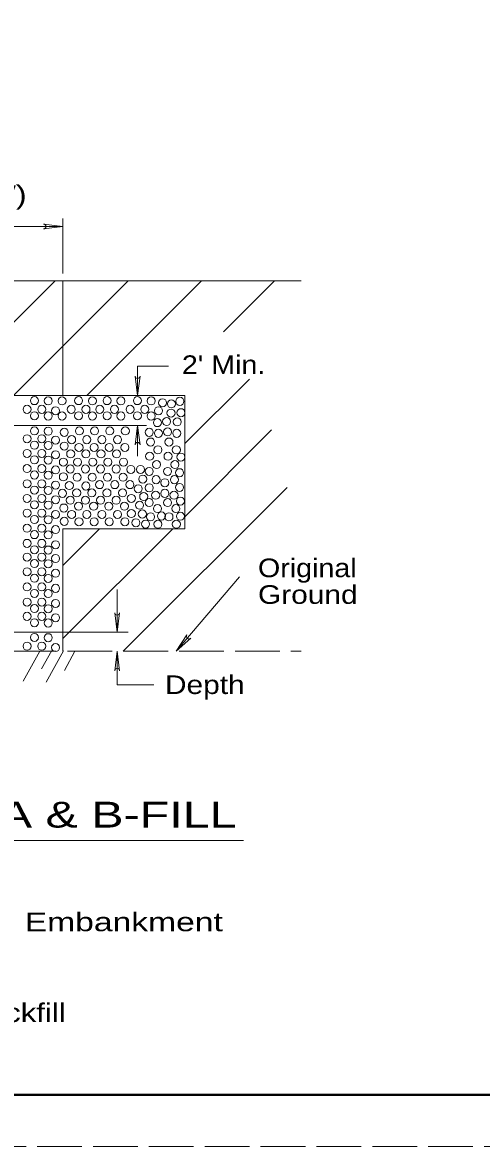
# Model space of a CAD drawing. Extents: x 750.7 to 784.7, y 834.8 to 878.8.
# Drawn here: x 758.61 to 763.05, y 834.78 to 845.66 of the extents above; entities that cross this region are included whole.
import ezdxf

# ---------------------------------------------------------------- set-up
doc = ezdxf.new("R2010")
doc.units = 0
doc.header["$LTSCALE"] = 0.072
doc.linetypes.add('LONG_DASHED', pattern=[7.5, 6, -1.5])
doc.layers.add('1', color=7, linetype='Continuous', lineweight=13)
doc.layers.add('47', color=7, linetype='Continuous', lineweight=13)

msp = doc.modelspace()

# ---------------------------------------------------------------- linework, layer by layer
at = {"layer": '1'}
for p, q in [((755.99883, 843.68525), (758.99883, 843.68525)), ((758.99883, 843.2315), (758.99883, 843.76325)), ((754.18342, 843.15875), (761.30275, 843.15875)), ((757.81558, 842.05058), (758.92367, 843.15875)), ((758.52258, 842.05058), (759.63067, 843.15875)), ((758.99883, 843.15875), (758.99883, 842.05058)), ((759.22958, 842.05058), (760.33775, 843.15875)), ((760.55258, 842.6665), (761.04483, 843.15875)), ((759.72125, 842.05058), (759.72125, 842.33475)), ((759.72125, 842.33475), (760.02133, 842.33475)), ((760.17767, 841.58442), (760.803, 842.20975)), ((754.82, 842.05058), (760.17767, 842.05058)), ((759.09983, 842.05058), (759.80117, 842.05058)), ((757.86583, 841.76058), (759.80658, 841.76058)), ((759.72125, 841.46442), (759.72125, 841.76058)), ((760.17767, 840.87725), (761.01733, 841.717)), ((759.58325, 839.5755), (761.16675, 841.15917)), ((758.99883, 840.76083), (758.99883, 839.5755)), ((758.99883, 840.40542), (759.35417, 840.76083)), ((758.99883, 839.69825), (760.06125, 840.76083)), ((760.0955, 839.5755), (760.70658, 840.29742)), ((759.52417, 839.76083), (759.52417, 840.17458)), ((757.72442, 839.76083), (759.63075, 839.76083)), ((758.77467, 839.57825), (758.61408, 839.28725)), ((758.89183, 839.58358), (758.79342, 839.40517)), ((759.00383, 839.57967), (758.83767, 839.2785)), ((759.11592, 839.57575), (759.01417, 839.39133)), ((754.44783, 837.74617), (760.7465, 837.74617))]:
    msp.add_line(p, q, dxfattribs=at)
at = {"layer": '1', "linetype": 'LONG_DASHED'}
msp.add_line((754.18342, 839.5755), (761.30275, 839.5755), dxfattribs=at)
at = {"layer": '1', "lineweight": 25}
msp.add_line((784.15083, 835.28433), (752.65083, 835.28433), dxfattribs=at)
at = {"layer": '1', "linetype": 'LONG_DASHED'}
msp.add_lwpolyline([(750.65083, 834.78433), (784.65083, 834.78433), (784.65083, 856.78433), (750.65083, 856.78433)], close=True, dxfattribs=at)
at = {"layer": '1', "lineweight": 40}
for points in [[(784.15083, 835.28433), (752.65083, 835.28433), (752.65083, 856.28433), (784.15083, 856.28433)], [(784.15083, 835.28433), (752.65083, 835.28433), (752.65083, 856.28433)]]:
    msp.add_lwpolyline(points, dxfattribs=at)
at = {"layer": '1'}
for points in [[(758.99883, 840.76083), (760.17767, 840.76083), (760.17767, 842.05058)], [(759.52417, 839.5755), (759.52417, 839.25108), (759.87925, 839.25108)]]:
    msp.add_lwpolyline(points, dxfattribs=at)
for centre in [(758.65305, 841.91636), (758.72408, 842.00072), (758.79508, 841.91639), (758.85724, 841.99839), (758.99141, 841.99839), (759.08013, 841.91636), (759.15116, 842.00072), (759.22216, 841.91639), (759.28433, 841.99839), (759.35538, 841.91636), (759.42641, 842.00072), (759.49741, 841.91639), (759.55958, 841.99839), (759.6483, 841.91636), (759.71933, 842.00072), (759.79033, 841.91639), (759.85249, 841.99839), (759.96266, 841.97993), (760.04799, 841.96927), (760.12974, 841.9941), (758.72408, 841.85422), (758.85724, 841.85189), (758.92824, 841.90306), (758.99141, 841.85189), (759.15116, 841.85422), (759.28433, 841.85189), (759.42641, 841.85422), (759.55958, 841.85189), (759.71933, 841.85422), (759.85249, 841.85189), (759.92349, 841.90306), (760.00174, 841.79852), (760.04441, 841.88035), (760.10483, 841.79502), (760.14041, 841.88393), (758.72408, 841.70764), (758.85724, 841.70531), (759.01253, 841.69424), (759.15903, 841.70757), (759.30545, 841.70757), (759.45195, 841.70757), (759.60286, 841.70757), (759.83362, 841.69425), (759.91291, 841.78785), (760.01112, 841.69866), (758.65305, 841.63211), (758.79508, 841.63214), (758.92824, 841.61881), (759.08361, 841.62324), (759.23003, 841.62324), (759.37653, 841.62324), (759.52745, 841.62324), (759.84703, 841.60015), (759.92245, 841.68449), (760.02453, 841.60015), (760.09995, 841.68449), (758.65305, 841.49003), (758.72408, 841.56997), (758.79508, 841.49006), (758.85724, 841.56764), (758.92824, 841.47672), (759.01253, 841.56107), (759.0747, 841.48557), (759.15461, 841.54774), (759.22111, 841.48557), (759.30103, 841.54774), (759.36761, 841.48557), (759.44753, 841.54774), (759.51853, 841.48557), (759.59845, 841.54774), (759.91803, 841.52465), (760.09553, 841.52465), (758.72408, 841.42789), (758.85724, 841.42556), (759.0037, 841.40565), (759.14128, 841.40565), (759.2877, 841.40565), (759.4342, 841.40565), (759.58511, 841.40565), (759.83811, 841.46249), (759.9047, 841.38257), (760.01561, 841.46249), (760.0822, 841.38257), (760.13987, 841.4545), (758.65305, 841.34353), (758.72408, 841.28139), (758.79508, 841.34356), (758.85724, 841.27906), (758.92824, 841.33022), (759.0037, 841.26357), (759.07028, 841.33907), (759.13686, 841.25915), (759.2167, 841.33907), (759.28328, 841.25915), (759.3632, 841.33907), (759.42978, 841.25915), (759.51411, 841.33907), (759.5807, 841.25915), (759.65603, 841.33458), (759.74928, 841.33458), (759.8337, 841.31599), (760.0112, 841.31599), (760.12653, 841.3035), (758.65305, 841.19694), (758.79508, 841.19697), (758.92824, 841.18364), (759.06136, 841.17924), (759.22112, 841.17475), (759.3542, 841.18808), (759.5007, 841.18808), (759.6472, 841.18808), (759.72703, 841.14808), (759.77145, 841.24133), (759.83362, 841.157), (759.90028, 841.23607), (759.98453, 841.20583), (760.07778, 841.23607), (760.12653, 841.16141), (758.65305, 841.05494), (758.72408, 841.13481), (758.79508, 841.05497), (758.85724, 841.13247), (758.92824, 841.04164), (758.99478, 841.10374), (759.07028, 841.03715), (759.13236, 841.10815), (759.2167, 841.03715), (759.27878, 841.10815), (759.3632, 841.03715), (759.42528, 841.10815), (759.51411, 841.03715), (759.5762, 841.10815), (759.66053, 841.05491), (759.78037, 841.07266), (759.89578, 841.08507), (759.98453, 841.10375), (760.07328, 841.08507), (758.72408, 840.99281), (758.85724, 840.99047), (759.00811, 840.96165), (759.1502, 840.9794), (759.29661, 840.9794), (759.44311, 840.9794), (759.59403, 840.9794), (759.74037, 840.98825), (759.8337, 841.01407), (759.91361, 840.95632), (760.0112, 841.01407), (760.09111, 840.95632), (760.13545, 841.02825), (758.65305, 840.91286), (758.72408, 840.85072), (758.79508, 840.91289), (758.85724, 840.84839), (758.92824, 840.89956), (759.01253, 840.8329), (759.08361, 840.89949), (759.15461, 840.8284), (759.23003, 840.89949), (759.30103, 840.8284), (759.37653, 840.89949), (759.44753, 840.8284), (759.52745, 840.89949), (759.59845, 840.8284), (759.66053, 840.90833), (759.70487, 840.81958), (759.76703, 840.90391), (759.84703, 840.8764), (759.95199, 840.88468), (760.02453, 840.8764), (760.13545, 840.88175), (758.65305, 840.76636), (758.79508, 840.76639), (758.92824, 840.75306), (759.79812, 840.80625), (759.91803, 840.80532), (760.09553, 840.80532), (758.65305, 840.61978), (758.72408, 840.70422), (758.79508, 840.61981), (758.85724, 840.70189), (758.92824, 840.60647), (758.72408, 840.55764), (758.85724, 840.55531), (758.65305, 840.48661), (758.72408, 840.42447), (758.79508, 840.48664), (758.85724, 840.42214), (758.92824, 840.47331), (758.65305, 840.34453), (758.72408, 840.28239), (758.79508, 840.34456), (758.85724, 840.28006), (758.92824, 840.33122), (758.65305, 840.19803), (758.79508, 840.19806), (758.92824, 840.18472), (758.72408, 840.13589), (758.85724, 840.13356), (758.65305, 840.05144), (758.72408, 839.98931), (758.79508, 840.05147), (758.85724, 839.98697), (758.92824, 840.03814), (758.65305, 839.91378), (758.72408, 839.85164), (758.79508, 839.91381), (758.85724, 839.84931), (758.92824, 839.90047), (758.65305, 839.62519), (758.72408, 839.70956), (758.79508, 839.62522), (758.85724, 839.70722), (758.92824, 839.61189)]:
    msp.add_circle(centre, 0.03892, dxfattribs=at)
at = {"layer": '47'}
for points in [[(758.81133, 843.66183), (758.99883, 843.68525), (758.81133, 843.70867)], [(759.74467, 842.23808), (759.72125, 842.05058), (759.69783, 842.23808)], [(759.69783, 841.57308), (759.72125, 841.76058), (759.74467, 841.57308)], [(759.54758, 839.94833), (759.52417, 839.76083), (759.50075, 839.94833)], [(760.2345, 839.7035), (760.0955, 839.5755), (760.19875, 839.73375)], [(759.50075, 839.388), (759.52417, 839.5755), (759.54758, 839.388)]]:
    msp.add_lwpolyline(points, dxfattribs=at)
for centre, start, end in [((758.81133, 843.68527), 270, 90), ((759.72124, 842.23809), 180, 0), ((759.72126, 841.57308), 0, 180), ((759.52416, 839.94834), 180, 0), ((760.21664, 839.71862), 139.75297, 319.75297), ((759.52417, 839.38799), 0, 180)]:
    msp.add_arc(centre, 0.02342, start, end, dxfattribs=at)

# ---------------------------------------------------------------- texts
at = {"layer": '1'}
for s, height, width, p in [('Trench Width (W)', 0.18, 1.3, (756.19767, 843.90283)), ("2' Min.", 0.18, 1.15, (760.14933, 842.2585)), ('Original', 0.18, 1.15, (760.88508, 840.29275)), ('Ground', 0.18, 1.2, (760.88508, 840.03475)), ('Depth', 0.18, 1.2, (759.98583, 839.16225)), ('CONDUIT, TYPE A & B-FILL', 0.25, 1.4, (754.6445, 837.87008)), ('-Construction Embankment', 0.18, 1.35, (756.60783, 836.86725)), ('-Structural Backfill', 0.18, 1.25, (756.60158, 835.98908))]:
    msp.add_text(s, height=height, dxfattribs=dict(at, width=width)).set_placement(p)

doc.saveas('drawing.dxf')
